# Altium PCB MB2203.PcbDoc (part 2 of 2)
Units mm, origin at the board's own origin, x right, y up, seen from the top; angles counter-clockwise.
Board outline 43 x 31 mm, 4 copper layers (Top Layer, Signal Layer 1, Signal Layer 2, Bottom Layer), stack 0.599 mm thick; 49 components, 37 nets, 166 pads, 723 vias.
Unrouted connection lines stored in the file: 92.
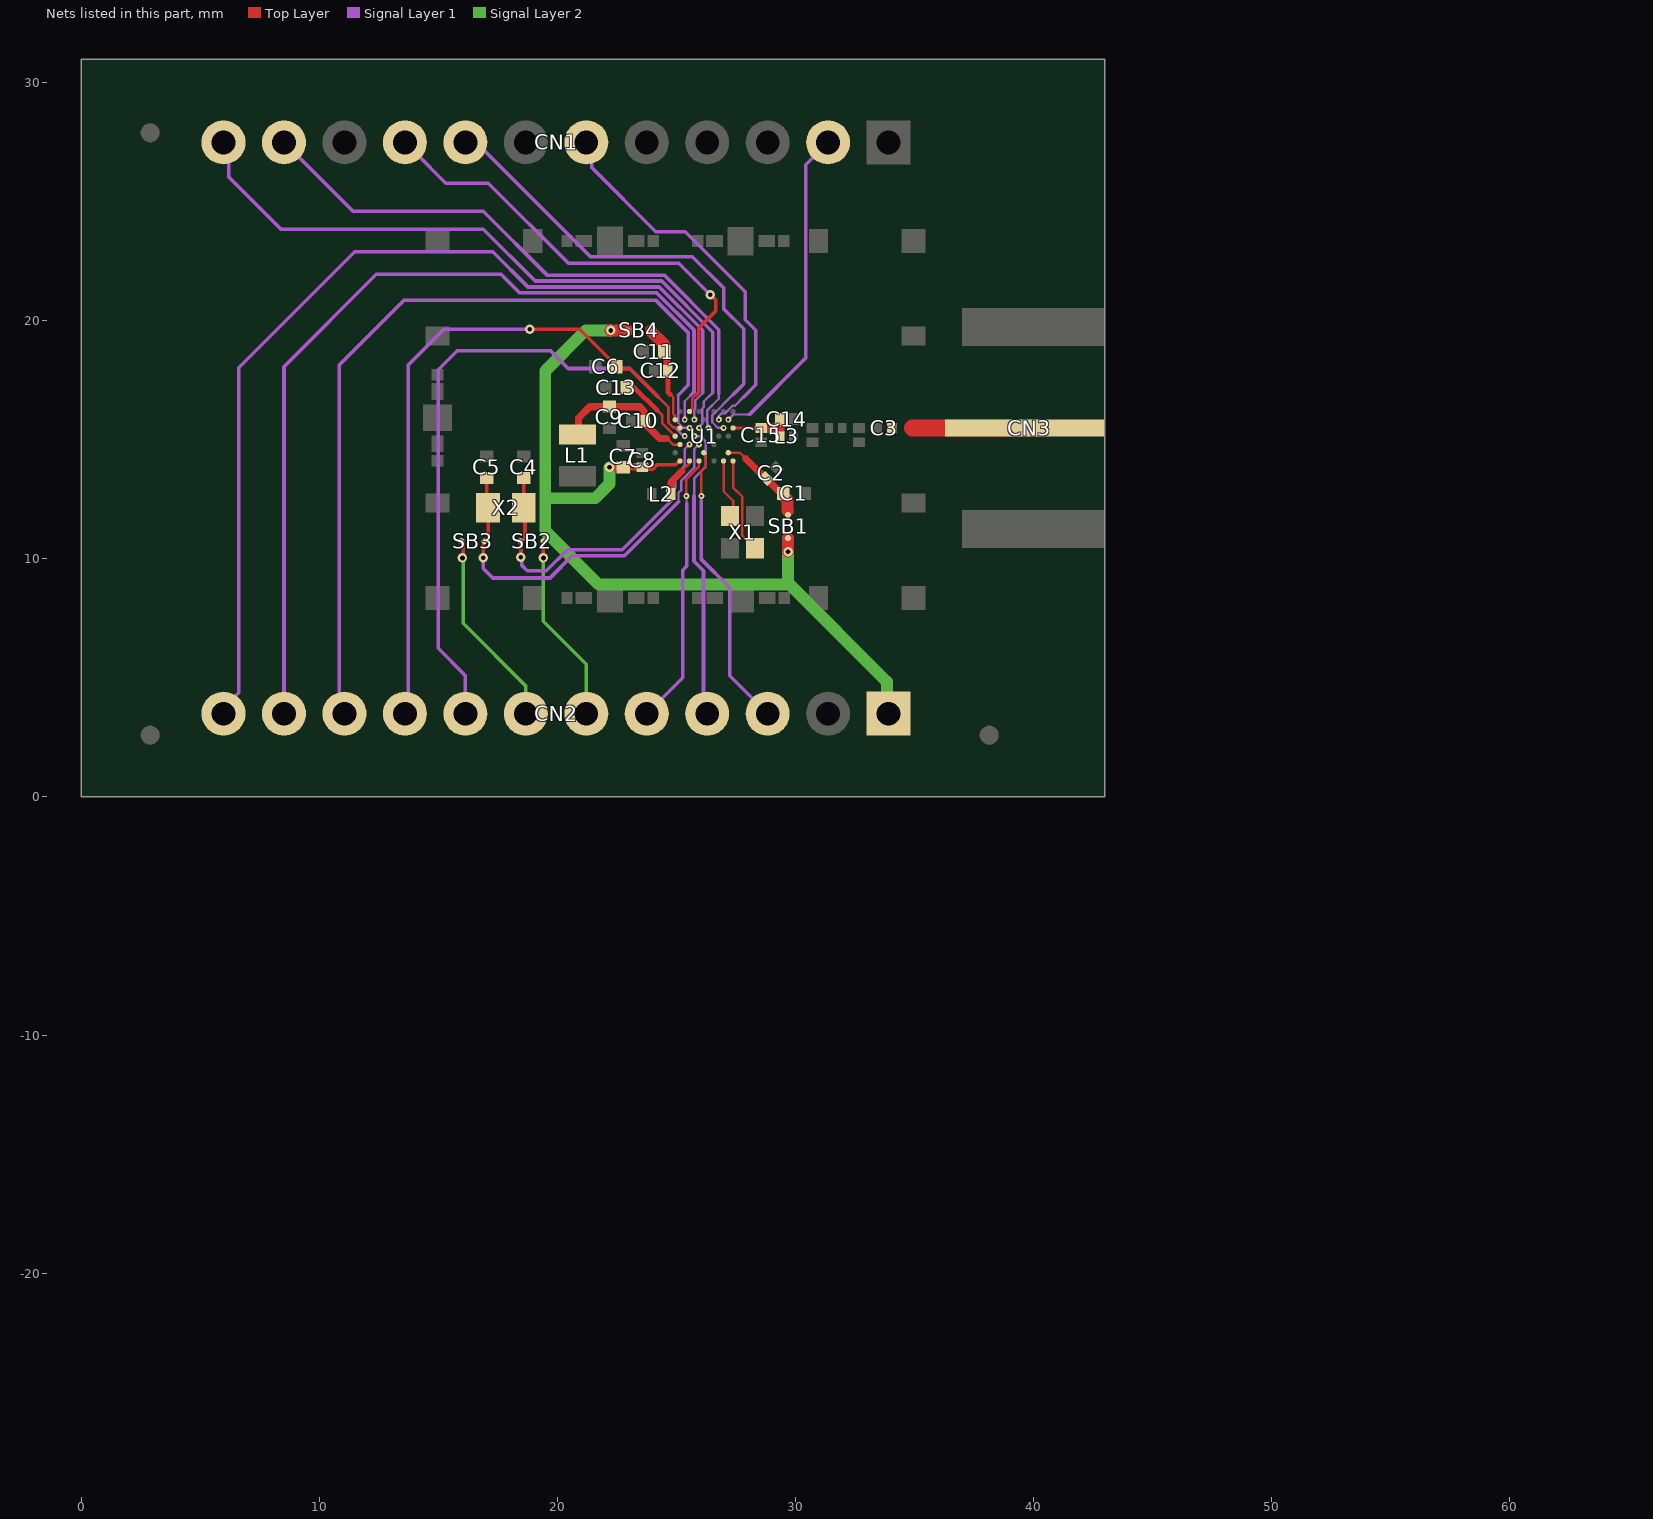
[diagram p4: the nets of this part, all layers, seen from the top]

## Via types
v1: diameter 0.4, hole 0.2, Top Layer to Bottom Layer, tented both sides, 709 vias
v2: diameter 0.25, hole 0.1, Top Layer to Signal Layer 1, tented both sides, 14 vias

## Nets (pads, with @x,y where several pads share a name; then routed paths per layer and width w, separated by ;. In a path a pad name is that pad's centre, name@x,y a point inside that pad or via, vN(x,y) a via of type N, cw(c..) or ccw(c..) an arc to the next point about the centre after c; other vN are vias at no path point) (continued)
PA9: CN1.6 U1.K6 | length 15.7
  Signal Layer 1 w0.1: v2(26.792,15.852) 26.792,16 26.902,16.109 27.047,16.109 27.374,16.436 27.466,16.436 27.828,16.798
  Signal Layer 1 w0.15: CN1.6@21.2,27.05 21.462,26.788 21.462,26.438 24.15,23.75 25.379,23.75 27.9,21.229 27.9,20.05 28.35,19.6 28.35,17.32 27.828,16.798
PA10: CN1.8 U1.L5 | length 20.5
  Signal Layer 1 w0.1: v2(26.993,15.506) 26.75,15.506 26.517,15.738 26.517,15.756 26.515,15.758 26.515,16.031 27.388,16.903
  Signal Layer 1 w0.15: CN1.8@16.145,27.5 16.456,27.189 16.911,27.189 21.4,22.7 25.681,22.7 26.992,21.389 26.992,20.508 27.836,19.664 27.836,17.352 27.388,16.903
PA11: CN1.2 U1.M6 | length 13.8
  Signal Layer 1 w0.1: v2(27.192,15.852) 27.413,16.066 27.454,16.066 28.032,16.057 ccw(c28.033,16.157) 28.033,16.057 28.067,16.057 28.081,16.07
  Signal Layer 1 w0.15: 28.081,16.07 30.45,18.439 30.45,26.565 CN1.2@31.385,27.5
PB0: CN1.9 U1.D7 | length 20.7
  Top Layer w0.1: U1.D7@25.563,16.199 25.563,16.226 25.683,16.347 25.683,16.741 25.845,16.903
  Top Layer w0.15: 25.845,16.903 25.952,17.009 25.952,19.702 26.671,20.421 26.671,20.868 v1(26.437,21.102)
  Signal Layer 1 w0.15: CN1.9@13.7,27.05 14.055,27.05 15.316,25.789 17.112,25.789 20.476,22.425 25.114,22.425 v1(26.437,21.102)
PB1: CN2.12 U1.E6 | length 41.4
  Signal Layer 1 w0.1: v2(25.763,15.852) 25.766,16.276 25.806,16.315 25.808,16.668 26.118,16.973
  Signal Layer 1 w0.15: CN2.12@6.1,3.6 6.1,3.855 6.625,4.38 6.625,18.025 11.5,22.9 12.8,22.9 13.007,22.9 17.3,22.9 18.775,21.425 24.293,21.425 26.118,19.6 26.118,16.973
PB2: CN2.10 U1.D5 | length 35.6
  Signal Layer 1 w0.1: 25.087,16.877 25.087,15.717 25.299,15.506 v2(25.563,15.506)
  Signal Layer 1 w0.15: CN2.10@11.065,3.5 10.85,3.715 10.85,18.15 13.575,20.875 24.136,20.875 25.5,19.511 25.5,17.289 25.087,16.877
PB3: CN2.11 U1.C6 | length 38.7
  Signal Layer 1 w0.1: v2(25.362,15.853) 25.363,16.625 25.616,16.878
  Signal Layer 1 w0.15: CN2.11@8.4,3.75 8.525,3.875 8.525,18.075 12.406,21.956 14.325,21.956 ; 13.706,21.956 17.1,21.956 ; 17.113,21.956 17.644,21.956 18.425,21.175 24.189,21.175 25.75,19.614 25.75,17.012 25.616,16.878
PB4: CN1.12 U1.F5 | length 28.8
  Signal Layer 1 w0.1: v2(25.963,15.506) 25.963,15.547 26.099,15.683 26.099,16.318 26.163,16.381 26.163,16.607 26.543,16.988
  Signal Layer 1 w0.15: CN1.12@5.85,27.35 6.212,26.988 6.212,26.038 8.4,23.85 16.9,23.85 19.075,21.675 24.396,21.675 26.543,19.528 26.543,16.988
PB5: CN1.11 U1.H5 | length 25.8
  Signal Layer 1 w0.1: v2(26.357,15.496) 26.329,15.525 26.329,15.645 26.299,15.674 26.299,16.235 26.793,16.729 26.793,16.939
  Signal Layer 1 w0.15: CN1.11@8.575,27.45 11.425,24.6 16.9,24.6 19.575,21.925 24.5,21.925 26.793,19.632 26.793,16.939
PB6: CN2.8 U1.C4 | length 27.5
  Signal Layer 1 w0.1: 24.236,16.814 24.669,16.381 24.669,15.736 24.899,15.506 24.966,15.506 25.313,15.16 v2(25.363,15.16)
  Signal Layer 1 w0.15: CN2.8@16.145,3.5 16.145,5.105 15,6.25 15,17.95 15.8,18.75 19.124,18.75 19.2,18.75 19.723,18.75 20.473,18 23.05,18 24.236,16.814
PB7: CN2.4 U1.E4 | length 12.4
  Signal Layer 1 w0.1: 25.753,12.661 25.753,13.384 26.237,13.868 26.237,14.933 26.011,15.16 v2(25.763,15.16)
  Signal Layer 1 w0.15: 25.75,12.661 25.75,9.9 26.15,9.5 26.15,3.655 CN2.4@26.305,3.5
PB12: CN2.6 SB2.2 | length 8
  Top Layer w0.15: v1@19.425,10.027 SB2.2@19.425,10.75
  Signal Layer 2 w0.15: v1(19.424,10.043) 19.424,7.376 21.225,5.575 CN2.6@21.225,3.5
PB13: CN2.7 SB3.2 | length 8.8
  Top Layer w0.15: v1@16.05,10.031 SB3.2@16.05,10.713
  Signal Layer 2 w0.15: v1@16.05,10.016 16.05,7.3 18.685,4.665 CN2.7@18.685,3.65 ; CN2.7@18.535,3.65 CN2.7@18.685,3.65 ; CN2.7@18.685,3.5 CN2.7@18.685,3.65 ; CN2.7@19.002,3.709 18.943,3.65 CN2.7@18.685,3.65
  other v1: 16.022,10.04
PB14: CN2.5 U1.F1 | length 11.5
  Top Layer w0.1: v2(25.428,12.646) 25.428,13.353 25.962,13.887 U1.F1@25.962,14.121
  Signal Layer 1 w0.1: v2(25.428,12.646) 25.437,12.637 25.437,12.33
  Signal Layer 1 w0.15: CN2.5@23.765,3.5 25.275,5.01 25.275,9.525 25.437,9.687 25.437,12.33
PB15: CN2.3 U1.G2 | length 12.2
  Top Layer w0.1: v2@26.062,12.649 26.062,13.693 26.24,13.871 26.24,14.342 26.162,14.419 U1.G2@26.162,14.467
  Signal Layer 1 w0.1: 26.062,12.45 v2(26.062,12.646)
  Signal Layer 1 w0.15: 26.062,12.45 26.062,9.977 27.25,8.789 27.25,5.095 CN2.3@28.845,3.5
RF_OUT: C14.1 C15.2 L3.1 U1.N5 | length 2.7
  Top Layer w0.135: U1.N5@27.392,15.5 C15.2@28.73,15.5
  Top Layer w0.2: L3.1@29.375,15.15 29.45,15.225 29.45,15.63 29.414,15.666 C14.1@29.414,15.832
  Top Layer w0.4: C15.2@28.58,15.5 29.25,15.5
RSTN: C6.1 CN2.9 U1.B5 | length 28.9
  Top Layer w0.1: 24.236,16.814 24.669,16.381 24.669,15.736 24.899,15.506 U1.B5@25.163,15.506
  Top Layer w0.15: v1(18.85,19.65) 20.95,19.65 22.457,18.143 22.457,17.993 23.057,17.993 24.236,16.814
  Signal Layer 1 w0.15: CN2.9@13.55,3.55 13.75,3.75 13.75,18.122 ; 13.75,18.15 15.25,19.65 v1(18.85,19.65)
SMA_IN: C3.2 CN3.1 | length 5.3
  Top Layer w0.7: 34.925,15.5 CN3.1@39.65,15.5 CN3.1@40.25,15.5
VCAP_A4: C13.2 U1.A4 | length 3.1
  Top Layer w0.1: 24.2,16.25 24.41,16.04 24.41,15.706 24.956,15.16 U1.A4@24.963,15.16
  Top Layer w0.2: C13.2@22.95,17.2 23.25,17.2 24.2,16.25
VDD: C7.2 C8.2 CN2.1 SB1.2 SB4.2 U1.B1 | length 37.8
  Top Layer w0.1: U1.B1@25.143,14.114 U1.B1@25.161,14.115
  Top Layer w0.15: 24.1,13.85 24.2,13.95 24.979,13.95 U1.B1@25.143,14.114
  Top Layer w0.3: v1(22.2,13.85) 22.85,13.85 22.9,13.9 22.925,13.875 23.575,13.875 23.6,13.85 24,13.85
  Top Layer w0.5: v1(22.25,19.6) SB4.2@22.95,19.6 ; v1(29.7,10.3) SB1.2@29.7,10.875
  Signal Layer 2 w0.5: 19.503,13.012 19.503,12.55 ; 19.503,13.034 19.503,17.894 21.209,19.6 v1(22.25,19.6) ; v1(22.2,13.85) 22.2,13.15 21.6,12.55 19.503,12.55 ; 29.7,8.925 29.699,8.924 21.752,8.924 19.503,11.172 19.503,12.55 ; v1@29.7,10.316 29.7,9 33.852,4.848 33.852,3.573 CN2.1@33.925,3.5
VDD2_A6_IN: C11.2 C12.2 SB4.1 U1.A6 | length 3.9
  Top Layer w0.1: 24.762,16.903 24.875,16.789 24.875,16.088 24.934,16.03 U1.A6@24.934,15.881
  Top Layer w0.2: C12.2@24.65,17.918 ccw(c24.451,17.933) C12.2@24.65,17.95 ; C12.2@24.658,17.677 24.658,17.007 24.762,16.903
  Top Layer w0.28: C11.2@24.5,18.75 24.6,18.65 24.6,18 C12.2@24.65,17.95
  Top Layer w0.5: SB4.1@23.94,19.6 23.94,19.57 24.495,19.015 24.495,18.755 C11.2@24.5,18.75
VDD_RF_M2_IN: C1.2 C2.2 SB1.1 U1.M2 | length 3.8
  Top Layer w0.1: U1.M2@27.192,14.467 27.674,14.467 27.917,14.224
  Top Layer w0.3: 27.917,14.224 C2.2@28.671,13.47 ; C2.2@28.738,13.488 28.738,13.431 C1.2@29.372,12.797 ; C1.2@29.4,12.85 29.505,12.745 C1.2@29.505,12.654
  Top Layer w0.5: C1.2@29.505,12.654 29.67,12.489 29.67,12.03 29.675,12.025 29.7,12.025
VFBSD_B3_IN: C9.2 C10.2 L1.1 U1.B3 | length 6.1
  Top Layer w0.1: 24.589,15.054 24.62,15.055 24.873,14.802 25.155,14.802 U1.B3@25.161,14.808
  Top Layer w0.3: L1.1@20.849,15.219 20.895,15.266 20.895,15.919 21.371,16.394 22.199,16.394 23.473,16.394 23.649,16.219 23.649,15.844 23.749,15.744 23.749,15.619 24.314,15.054 24.589,15.054
VLXSD_D1_OUT: L2.2 U1.D1 | length 1.7
  Top Layer w0.1: 25.25,13.727 25.277,13.727 25.534,13.984 25.534,14.092 U1.D1@25.562,14.12
  Top Layer w0.3: L2.2@24.775,12.725 24.78,12.73 24.78,13.23 25.25,13.7
XTAL_32K_0: C4.1 SB2.1 U1.D3 X2.1 | length 14.1
  Top Layer w0.15: v1(18.475,10.075) 18.482,10.082 18.482,10.61 ; SB2.1@18.5,10.725 18.65,10.875 18.65,12.15 X2.1@18.8,12.15 ; X2.1@18.6,12.15 C4.1@18.6,13.4
  Signal Layer 1 w0.1: 24.776,12.429 24.79,12.444 24.79,12.821 24.972,13.003 24.972,13.536 25.364,13.928 25.364,14.615 v2(25.563,14.813)
  Signal Layer 1 w0.15: v1(18.475,10.075) 18.523,10.027 18.523,9.727 18.75,9.5 19.55,9.5 20.439,10.389 22.735,10.389 24.776,12.429
XTAL_32K_1: C5.2 SB3.1 U1.F3 X2.2 | length 16.5
  Top Layer w0.15: v1@16.9,9.991 v1(16.9,10.05) 16.9,10.615 17.025,10.74 SB3.1@17.025,10.75 ; X2.2@17.05,12.2 C5.2@17.05,13.4 ; 17.1,10.75 17.1,11.95 17.3,12.15 X2.2@17.25,12.2
  Signal Layer 1 w0.1: 25.1,12.4 25.1,12.778 25.222,12.9 25.222,13.296 25.763,13.836 25.763,14.613 v2(25.963,14.813)
  Signal Layer 1 w0.15: v1@16.9,10.024 16.9,9.6 17.3,9.2 19.7,9.2 20.628,10.128 22.828,10.128 25.1,12.4
XTAL_32M_IN: U1.L1 X1.1 | length 2.5
  Top Layer w0.1: U1.L1@26.992,14.12 26.992,12.845 27.392,12.445 27.392,11.934 X1.1@27.258,11.8
XTAL_32M_OUT: U1.N1 X1.3 | length 4
  Top Layer w0.1: U1.N1@27.392,14.12 27.392,13 27.783,12.609 27.783,10.975 X1.3@28.308,10.45
pads on no net: MIRE1.1 MIRE2.1 MIRE3.1 MIRE4.1 MIRE5.1 MIRE6.1

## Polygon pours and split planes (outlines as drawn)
GND on Bottom Layer "NONET_L-01_P-001" (solid, remove dead copper, pour order 9): 0,0 43,0 43,31 0,31
GND on Signal Layer 2 "NONET_L-01_P-001" (solid, remove dead copper, pour order 1): 0,31 0,0 43,0 43,31
GND on Top Layer "NONET_L-01_P-001" (solid, pour order 8): 0,31 0,0 43,0 43,31
GND on Signal Layer 1 "GND_L02_P005" (solid, remove dead copper, pour order 5): 0,31 0,0 43,0 43,31

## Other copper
Top Layer:
  pour cut-out: 33.9,15.8 34.75,16.25 43,16.25 43,14.75 34.75,14.75 33.9,15.2 28.393,15.2 28.393,15.8
  region net SMA_IN: 34.2,15.686 34.789,15.85 35.153,15.85 35.153,15.15 34.793,15.15 34.2,15.322
  region net MATCHING_CELL_1: 30.311,15.501 29.884,15.168 29.884,15.832
  region net RF_OUT: 28.987,15.499 29.414,15.832 29.414,15.168
  pour cut-out: 29.167,16.087 30.117,16.087 30.117,14.917 29.167,14.917
  pour cut-out: 24.175,13.075 24.575,13.075 24.575,12.375 24.175,12.375
  pour cut-out: 28.182,14.132 29.135,14.132 29.136,14.207 28.182,14.207
  pour cut-out: 27.27,15.2 27.392,15.078 27.85,15.078 27.85,13.919 27.456,13.526 24.382,13.526 24.382,16.854 27.27,16.854 27.27,15.7
  pour cut-out: 19.975,14.875 21.725,14.875 21.725,13.825 19.975,13.825
  pour cut-out: 27.392,15.768 28.446,15.768 28.451,15.232 27.392,15.232
  pour cut-out: 28.953,14.169 29.135,14.17 29.149,15.35 28.953,15.35
  region net GND: 27.637,15.1 27.637,15.232 28.25,15.232 28.25,14.487
  region net GND: 28.25,15.1 28.965,15.1 28.965,14.321 28.936,14.292 28.445,14.292 28.25,14.487
  text "1" at 40.731,4.325 h2 r90
  text ".Layer_Name" at 3.5,-21.3 h3
  text ".GTL" at 45.195,-21.3 h3
Signal Layer 1:
  pour cut-out: 29.15,16.25 42.998,16.25 43.003,14.75 29.15,14.75
  pour cut-out: 23.31,16.14 24.8,14.65 24.8,13.855 21.65,13.855 21.65,16.14
  pour cut-out: 28.4,15.85 29.275,15.85 29.278,14.75 28.4,14.75
  pour cut-out: 27.521,13.538 26.287,13.538 26.296,13.546 26.296,14.96 26.661,15.325 27.207,15.325 27.207,15.632 27.265,15.69 27.265,15.692 27.521,15.692
  pour cut-out: 19.102,20.548 17.448,22.202 17.773,22.527 19.427,20.873
  pour cut-out: 18.168,23.232 17.843,22.907 16.8,23.95 17.125,24.275
  text "2" at 40.731,5.382 h2 r90
  text ".Layer_Name" at 3.5,-21.3 h3
  text ".G1" at 45.195,-21.3 h3
Signal Layer 2:
  pour cut-out: 23.31,16.14 24.8,14.65 24.8,13.855 21.8,13.855 21.8,16.14
  pour cut-out: 27.521,13.537 26.305,13.537 26.296,13.546 26.296,14.96 26.661,15.325 27.207,15.325 27.207,15.632 27.267,15.692 27.521,15.692
  text "3" at 40.731,6.832 h2 r90
  text ".Layer_Name" at 3.425,-21.3 h3
  text ".G2" at 45.12,-21.3 h3
Bottom Layer:
  text "4" at 40.725,8.975 h2 r90
  text ".GBL" at 33.992,-21.332 h3
  text ".Layer_Name" at 75.306,-21.332 h3
Multi-Layer:
  pour cut-out: 39.15,9.5 41.15,9.5 41.15,3.85 39.15,3.85

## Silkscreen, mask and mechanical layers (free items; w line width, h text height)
Top Overlay:
  lines w0.2: 21.275,16.575 21.63,16.575 21.615,16.56 ; 22.255,12.3 22.255,13.35 22.405,13.5
  text "MB2203B" at 11.975,9.5 h3 r90
  text ".Layer_Name" at 3.5,-21.3 h3
  text ".GTO" at 45.195,-21.3 h3
Bottom Overlay:
  text "E" at 2.691,26.469 h9 r270
  text "RX" at 13.125,24.119 h1.5 r270
  text "TX" at 23.406,24.119 h1.5 r270
  text "GND" at 33.504,23.083 h1.5 r270
  text "PA10" at 15.703,22.737 h1.5 r270
  text "SWDIO" at 18.676,21.333 h1.5 r270
  text "SWCLK" at 10.591,21.225 h1.5 r270
  text "H" at 2.406,18.725 h10 r270
  text "I" at 2.982,10.306 h9 r270
  text "GND" at 30.941,5.125 h1.5 r270
  text "RSTN" at 13.191,5.1 h1.5 r270
  text "VDD" at 33.325,5.101 h1.5 r270
  text ".GBO" at 33.992,-21.332 h3
  text ".Layer_Name" at 75.306,-21.332 h3
Top Paste:
  text ".Layer_Name" at 3.473,-21.29 h3
  text ".GTP" at 45.168,-21.29 h3
Bottom Paste:
  text ".GBP" at 33.883,-21.317 h3
  text ".Layer_Name" at 75.197,-21.317 h3
Top Solder:
  region: 39.15,9.504 39.15,3.84 41.15,3.84 41.15,9.504
  region: 30.099,14.816 30.099,14.828
  text ".Layer_Name" at 3.498,-21.365 h3
  text ".GTS" at 45.193,-21.365 h3
Bottom Solder:
  text ".GBS" at 33.908,-21.392 h3
  text ".Layer_Name" at 75.222,-21.392 h3
M1-Board Shape:
  lines w0.1: 0,0 43,0 43,31 0,31 0,0 ; 0,0 0,0 ; 40.75,31 40.75,31
M2-Board Dimensions:
  text ".Layer_Name" at 3.5,-21.3 h3
  text ".GM2" at 45.195,-21.3 h3
M14-Top Assembly:
  text ".Layer_Name" at 3.5,-21.3 h3
  text ".GM14" at 45.195,-21.3 h3
M15-Bottom Assembly:
  text ".GM15" at 33.992,-21.332 h3
  text ".Layer_Name" at 75.306,-21.332 h3
Drill Drawing:
  drawing of 196 lines, arcs and shapes, not listed
  text "PCB SPECIFICATIONS :" at -2.5,74.35 h3
  text "PCB : TYPE 3" at 145.912,74.118 h3
  text "A.   MATERIAL :" at -2.5,70.35 h3
  text "FR-4" at 36,70.35 h3
  text "TG-170" at 52.5,70.35 h3
  text "X  TG-150" at 70.75,70.35 h3
  text "TG-140" at 86.75,70.35 h3
  text "ASPECT-RATIO, AXE Z :" at 145.912,68.618 h3
  text "B.   MATERIAL FAMILY :" at -2.5,67.35 h3
  text "N/A" at 36,67.35 h3
  text "C.   SOLDERMASK COLOR :" at -2.5,64.35 h3
  text "GREEN" at 36,64.35 h3
  text "X  WHITE" at 52.5,64.35 h3
  text "RED" at 70.75,64.35 h3
  text "BLACK" at 86.75,64.35 h3
  text "6:1 to 8:1 / LEVEL \"B\"" at 145.93,61.87 h3
  text "D.   SILKSCREEN COLOR :" at -2.5,61.35 h3
  text "WHITE" at 36,61.35 h3
  text "YELLOW" at 52.5,61.35 h3
  text "BLACK" at 70.75,61.35 h3
  text "X  Blue ink PANTONE 2955" at 86.75,61.35 h3
  text "E.   SURFACE FINISH :" at -2.5,58.35 h3
  text "X  ENIG" at 36,58.35 h3
  text "IMMERSION SILVER" at 52.5,58.35 h3
  text "IMMERSION TIN" at 86.75,58.35 h3
  text "MINIMUM PARAMETERS" at 145.957,56.269 h3
  text "HASL" at 36,55.35 h3
  text "HASL (PB-FREE)" at 52.5,55.35 h3
  text "GOLDEN FINGER" at 86.75,55.35 h3
  text "F.   IMPEDANCE CONTROL :" at -2.5,52.35 h3
  text "NO" at 36,52.35 h3
  text "X  YES  (SEE IMPEDANCE TABLE FOR DETAIL INFORMATION)" at 52.5,52.35 h3
  text "DEFAULT" at 145.957,50.769 h3
  text "G.   THROUGH VIA :" at -2.5,49.35 h3
  text "PLUG THE VIAS WHICH ARE COVERED WITH SOLDERMASK ONE OR TWO SIDE." at 36,49.35 h3
  text "PLUG MATERIAL :" at 36,46.35 h3
  text "X  SOLDERMASK" at 61.5,46.35 h3
  text "NON-CONDUCTIVE EPOXY." at 86.75,46.35 h3
  text "TRACKS : 0.1mm           / GAPS : 0.1mm" at 145.957,45.019 h3
  text "H.   STACK-UP :" at -2.5,43.35 h3
  text "SEE LAYER STACK-UP SEQUENCE FOR OVERALL THICKNESS." at 36,43.35 h3
  text "Layer" at 92.651,35.624 h1.52
  text "Name" at 99.027,35.624 h1.52
  text "Material" at 111.35,35.624 h1.52
  text "Thickness" at 124.613,35.624 h1.52
  text "Constant" at 133.71,35.624 h1.52
  text "Top Overlay" at 99.027,32.576 h1.52
  text "Top Solder" at 99.027,29.528 h1.52
  text "Solder Resist" at 111.35,29.528 h1.52
  text "0.020mm" at 124.613,29.528 h1.52
  text "3.5" at 133.71,29.528 h1.52
  text "1" at 92.651,26.48 h1.52
  text "Top Layer" at 99.027,26.48 h1.52
  text "0.035mm" at 124.613,26.48 h1.52
  text "Dielectric 1" at 99.027,23.432 h1.52
  text "TU-768 (1x2113)" at 111.35,23.432 h1.52
  text "0.102mm" at 124.613,23.432 h1.52
  text "4.2" at 133.71,23.432 h1.52
  text "2" at 92.65,20.384 h1.52
  text "Signal Layer 1" at 99.027,20.384 h1.52
  text "0.036mm" at 124.613,20.384 h1.52
  text "Dielectric2" at 99.027,17.336 h1.52
  text "Tu-768 (2x2113)" at 111.35,17.336 h1.52
  text "0.254mm" at 124.613,17.336 h1.52
  text "4.3" at 133.71,17.336 h1.52
  text "3" at 92.651,14.288 h1.52
  text "Signal Layer 2" at 99.027,14.288 h1.52
  text "0.036mm" at 124.613,14.288 h1.52
  text "Dielectric3" at 99.027,11.24 h1.52
  text "TU-768 (1x2113)" at 111.35,11.24 h1.52
  text "0.102mm" at 124.613,11.24 h1.52
  text "4.2" at 133.71,11.24 h1.52
  text "4" at 92.651,8.192 h1.52
  text "Bottom Layer" at 99.027,8.192 h1.52
  text "0.035mm" at 124.613,8.192 h1.52
  text "Bottom Solder" at 99.027,5.144 h1.52
  text "Solder Resist" at 111.35,5.144 h1.52
  text "0.020mm" at 124.613,5.144 h1.52
  text "3.5" at 133.71,5.144 h1.52
  text "Bottom Overlay" at 99.027,2.096 h1.52
  text "Total board thickness:" at 92.651,-0.952 h1.52
  text "0.639mm" at 124.613,-0.952 h1.52
  text "Symbol" at 92.436,-10.722 h1.83
  text "Count" at 99.6,-10.722 h1.83
  text "Hole Size" at 107.022,-10.722 h1.83
  text "Plated" at 120.846,-10.722 h1.83
  text "Hole Type" at 127.137,-10.722 h1.83
  text "Drill Layer Pair" at 136.292,-10.722 h1.83
  text "Via/Pad" at 157.781,-10.722 h1.83
  text "Pad Shape" at 165.282,-10.722 h1.83
  text "Template" at 175.082,-10.722 h1.83
  text "Hole Length" at 183.694,-10.722 h1.83
  text "Routed Path Length" at 194.172,-10.722 h1.83
  text "14" at 99.6,-13.882 h1.52
  text "0.100mm (3.94mil)" at 107.022,-13.882 h1.52
  text "PTH" at 120.846,-13.882 h1.52
  text "Round" at 127.137,-13.882 h1.52
  text "[uVia] Top Layer - Signal Layer 1" at 136.292,-13.882 h1.52
  text "Via" at 157.781,-13.882 h1.52
  text "Rounded" at 165.282,-13.882 h1.52
  text "v25h10m0" at 175.082,-13.882 h1.52
  text "-" at 183.694,-13.882 h1.52
  text "-" at 194.172,-13.882 h1.52
  text "24" at 99.6,-17.042 h1.52
  text "1.000mm (39.37mil)" at 107.022,-17.042 h1.52
  text "PTH" at 120.846,-17.042 h1.52
  text "Round" at 127.137,-17.042 h1.52
  text "Top Layer - Bottom Layer" at 136.292,-17.042 h1.52
  text "Pad" at 157.781,-17.042 h1.52
  text "Rounded" at 165.282,-17.042 h1.52
  text "(Mixed)" at 175.082,-17.042 h1.52
  text "-" at 183.694,-17.042 h1.52
  text "-" at 194.172,-17.042 h1.52
  text "709" at 99.6,-20.202 h1.52
  text "0.200mm (7.87mil)" at 107.022,-20.202 h1.52
  text "PTH" at 120.846,-20.202 h1.52
  text "Round" at 127.137,-20.202 h1.52
  text "Top Layer - Bottom Layer" at 136.292,-20.202 h1.52
  text "Via" at 157.781,-20.202 h1.52
  text "Rounded" at 165.282,-20.202 h1.52
  text "(Mixed)" at 175.082,-20.202 h1.52
  text "-" at 183.694,-20.202 h1.52
  text "-" at 194.172,-20.202 h1.52
  text ".Layer_Name" at 3.5,-21.3 h3
  text ".DRL" at 45.195,-21.3 h3
  text "747 Total" at 99.6,-23.362 h1.52
M20-Top Title Box:
  circle w0.254: c81.504,-28.021 r1.3
  region: 81.03,-20.784 65.502,-20.784 64.808,-22.56 63.597,-23.785 62.2,-21.925 62.2,-20.274 63.343,-18.877 64.779,-18.498 81.03,-18.498
  region: 67.026,-29.114 56.27,-29.114 57.264,-26.621 65.121,-26.621 65.57,-25.862 67.779,-28.41
  lines w0.254: 57.264,-26.621 66.056,-26.621 62.989,-23.083 cw(c64.793,-21.139) 65.033,-18.498 81.797,-18.498 81.035,-20.784 ; 60.577,-18.251 cw(c63.004,-19.222) 63.24,-16.619 ; 60.617,-18.219 56.27,-29.114 75.593,-29.114 ccw(c75.842,-26.379) 78.391,-27.399 ; 62.356,-22.153 67.779,-28.41 ; 62.61,-22.153 67.915,-28.275 ; 62.61,-21.899 67.915,-28.021 ; 62.708,-20.784 75.701,-20.784 ; 62.737,-21.772 68.042,-27.894 ; 62.864,-21.645 68.169,-27.767 ; 62.991,-21.518 68.296,-27.64 ; 63.118,-21.391 68.423,-27.513 ; 63.173,-19.439 68.478,-25.56 ; 63.241,-16.619 82.691,-16.619 78.392,-27.397 ; 63.245,-21.264 68.496,-27.323 ; 63.245,-21.01 68.55,-27.132 ; 63.245,-20.756 68.55,-26.878 ; 63.245,-19.867 68.55,-25.989 ; 63.372,-20.629 68.677,-26.751 ; 63.372,-20.248 68.677,-26.37 ; 64.744,-26.634 ccw(c64.849,-26.099) 65.147,-25.642 ; 65.831,-20.771 ccw(c65.805,-21.338) 65.474,-21.8 67.839,-24.529 cw(c66.035,-26.473) 66.768,-29.022 ; 72.112,-28.91 75.001,-20.53 ; 72.334,-28.86 75.203,-20.539 ; 72.461,-28.86 75.33,-20.539 ; 72.715,-28.86 75.584,-20.539 ; 72.969,-28.86 75.838,-20.539 ; 73.223,-28.86 76.092,-20.539 ; 73.477,-28.86 76.346,-20.539 ; 73.731,-28.86 76.6,-20.539 ; 73.985,-28.86 76.854,-20.539 ; 74.239,-28.86 77.108,-20.539 ; 74.448,-28.91 77.337,-20.53 ; 77.337,-20.784 81.03,-20.784 ; 80.361,-20.782 81.123,-18.496 ; 80.527,-20.784 81.289,-18.498 ; 80.781,-20.784 81.543,-18.498
  lines w0.3: -5.5,-33 84.5,-33 84.5,-13 -5.5,-13 ; -5.5,-28 54.5,-28 ; -5.5,-23 54.5,-23 ; -5.5,-18 54.5,-18 ; -5.5,-33 -5.5,-13 ; 34.5,-33 34.5,-18 ; 54.5,-33 54.5,-13 ; 72.112,-28.91 74.448,-28.91
  text "Project: '.Board_Name'" at -4.5,-16.216 h3
  text "Layer:" at -4.5,-21.3 h3
  text "Gerber:" at 35.489,-21.3 h3
  text "Variant: '.VariantName'" at -4.5,-26.3 h3
  text "'.Board_Reference'" at 35.616,-26.3 h3
  text "R" at 80.996,-28.783 h1.52
  text "Date: '.Board_Document_Date'" at -4.5,-31.3 h3
  text "Rev: '.Board_PCB_Revision'" at 35.559,-31.3 h3
M21-Bottom Title Box:
  circle w0.254: c-2.317,-28.021 r1.3
  region: 12.161,-29.114 22.917,-29.114 21.924,-26.621 14.066,-26.621 13.617,-25.862 11.409,-28.41
  region: -1.842,-20.784 13.685,-20.784 14.379,-22.56 15.59,-23.785 16.987,-21.925 16.987,-20.274 15.844,-18.877 14.408,-18.498 -1.842,-18.498
  lines w0.254: -2.356,-18.498 -1.594,-20.784 ; -2.102,-18.498 -1.34,-20.784 ; -1.936,-18.496 -1.174,-20.782 ; -1.848,-20.784 -2.61,-18.498 14.154,-18.498 cw(c14.394,-21.139) 16.198,-23.083 13.132,-26.621 21.924,-26.621 ; -1.842,-20.784 1.85,-20.784 ; 0.795,-27.397 -3.504,-16.619 15.946,-16.619 ; 0.796,-27.399 ccw(c3.346,-26.379) 3.594,-29.114 22.917,-29.114 18.571,-18.219 ; 1.85,-20.53 4.739,-28.91 ; 2.079,-20.539 4.948,-28.86 ; 2.333,-20.539 5.202,-28.86 ; 2.587,-20.539 5.456,-28.86 ; 2.841,-20.539 5.71,-28.86 ; 3.095,-20.539 5.964,-28.86 ; 3.349,-20.539 6.218,-28.86 ; 3.486,-20.784 16.479,-20.784 ; 3.603,-20.539 6.472,-28.86 ; 3.857,-20.539 6.726,-28.86 ; 3.984,-20.539 6.853,-28.86 ; 4.186,-20.53 7.075,-28.91 ; 10.51,-26.751 15.815,-20.629 ; 10.51,-26.37 15.815,-20.248 ; 10.637,-27.132 15.942,-21.01 ; 10.637,-26.878 15.942,-20.756 ; 10.637,-25.989 15.942,-19.867 ; 10.691,-27.323 15.942,-21.264 ; 10.709,-25.56 16.014,-19.439 ; 10.764,-27.513 16.069,-21.391 ; 10.891,-27.64 16.196,-21.518 ; 11.018,-27.767 16.323,-21.645 ; 11.145,-27.894 16.45,-21.772 ; 11.272,-28.275 16.577,-22.153 ; 11.272,-28.021 16.577,-21.899 ; 11.409,-28.41 16.831,-22.153 ; 12.419,-29.022 cw(c13.152,-26.473) 11.348,-24.529 13.713,-21.8 ccw(c13.383,-21.338) 13.357,-20.771 ; 14.04,-25.642 ccw(c14.338,-26.099) 14.443,-26.634 ; 15.947,-16.619 cw(c16.184,-19.222) 18.61,-18.251
  lines w0.3: 4.739,-28.91 7.075,-28.91 ; 24.5,-33 24.5,-13 ; 24.5,-28 84.5,-28 ; 24.5,-23 84.5,-23 ; 24.5,-18 84.5,-18 ; 44.5,-33 44.5,-18 ; -5.5,-33 84.5,-33 84.5,-13 -5.5,-13 -5.5,-33
  text "Project: '.Board_Name'" at 83.306,-16.216 h3
  text "Gerber:" at 43.317,-21.3 h3
  text "Layer:" at 83.306,-21.3 h3
  text "'.Board_Reference'" at 43.317,-26.3 h3
  text "Variant: '.VariantName'" at 83.306,-26.3 h3
  text "R" at -1.809,-28.783 h1.52
  text "Rev: '.Board_PCB_Revision'" at 43.374,-31.3 h3
  text "Date: '.Board_Document_Date'" at 83.306,-31.3 h3

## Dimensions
0,31 to 43,31 on M2-Board Dimensions
0,31 to 0,0 on M2-Board Dimensions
